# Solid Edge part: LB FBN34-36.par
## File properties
Title: Locating Bush
Author: Dan
Template: Locating Bush.par
Last saved by: Dan
Revision: 8
Application: Solid Edge
Density: 0.000007833 kg/mm^3
Accuracy: 0.99
Document Number: CV
Material: Steel
Face Style: Steel
Fill Style: ANSI32(Steel)
Virtual Style: Machined steel
Coef. of Thermal Exp: 1.3e-05
Thermal Conductivity: 32.0
Specific Heat: 481.0
Modulus of Elasticity: 199947953000.0
Poisson's Ratio: 0.29
Yield Stress: 262000766.0
Ultimate Stress: 358527364.0
Elongation: 0.0
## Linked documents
FBN34-36.par
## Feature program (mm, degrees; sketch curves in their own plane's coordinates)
part copy "CopiedPart_1"
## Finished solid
Body 1: solid body, 10 faces, 10 edges, 0 vertices.
  Faces by surface: cone 4, cylinder 3, plane 3
  Edges by curve: circle 10
Bounding box of the edges (mm): 36.000 x 46.000 x 46.000, from (-36, -23, -23) to (0, 23, 23).
Cylindrical faces by radius (mm): R17 x1, R21 x1, R23 x1
Conical faces (half-angle, radius in mm at the cone's reference point): 45 deg R17 x1, 45 deg R18 x1, 45 deg R20 x1, 45 deg R23 x1
Planar faces by outward normal: +x 1, -x 2
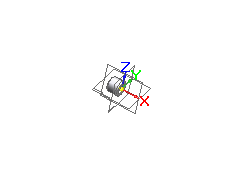
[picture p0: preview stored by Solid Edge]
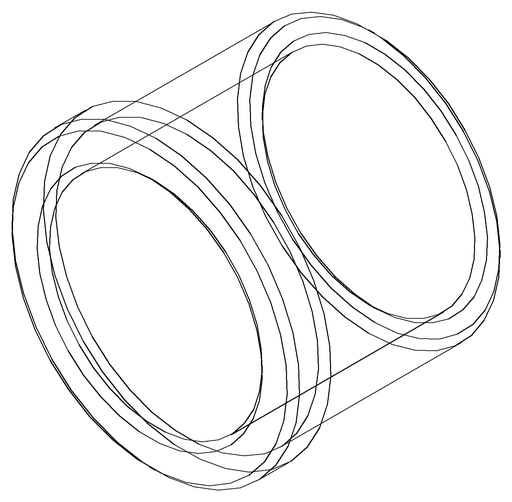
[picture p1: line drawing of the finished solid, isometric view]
